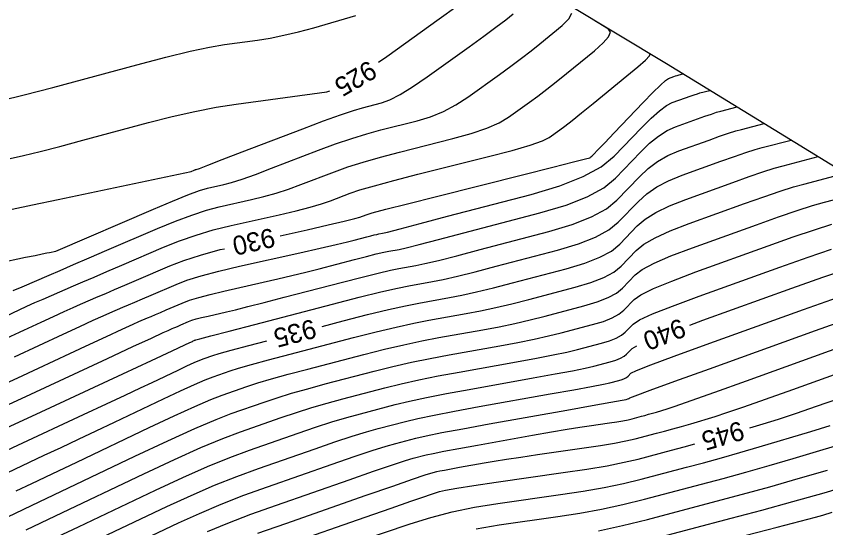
# Model space of a CAD drawing. Extents: x 2175772 to 2185556, y 721391 to 722853.
# Drawn here: x 2178888.4 to 2179007.5, y 722098.3 to 722173.5 of the extents above; entities that cross this region are included whole.
import ezdxf

# ---------------------------------------------------------------- set-up
doc = ezdxf.new("R2010")
doc.units = 0
for name, color, linetype in [('DT_X_Contour_Major', 7, 'Continuous'), ('DT_X_Contour_Minor', 7, 'Continuous'), ('DT_X_TIN_Hull', 7, 'Continuous')]:
    doc.layers.add(name, color=color, linetype=linetype)

msp = doc.modelspace()

# ---------------------------------------------------------------- linework, layer by layer
at = {"layer": 'DT_X_Contour_Major'}
for points in [[(2178941.68, 722166.78), (2178942.86, 722167.62), (2178950.57, 722173.15), (2178953.17, 722175.02), (2178955.21, 722176.5), (2178956.67, 722177.59), (2178957.56, 722178.28), (2178959.18, 722179.6), (2178959.51, 722180.16), (2178959.28, 722180.85), (2178958.49, 722181.66), (2178957.15, 722182.6), (2178949.59, 722187.28)], [(2178927.18, 722141.26), (2178931.14, 722142.15), (2178934.27, 722142.86), (2178936.62, 722143.41), (2178938.16, 722143.79), (2178938.9, 722144), (2178939.82, 722144.36), (2178940.72, 722144.62), (2178942.75, 722145.16), (2178945.9, 722145.97), (2178950.17, 722147.05), (2178963.06, 722150.3), (2178967.29, 722151.36), (2178970.32, 722152.13), (2178972.13, 722152.59), (2178972.75, 722152.75), (2178972.77, 722152.76), (2178972.79, 722152.78), (2178972.82, 722152.8), (2178972.85, 722152.83), (2178972.9, 722152.87), (2178973.05, 722152.98), (2178973.29, 722153.23), (2178973.92, 722153.89), (2178974.94, 722154.95), (2178976.34, 722156.41), (2178980.59, 722160.87), (2178982.02, 722162.34), (2178983.12, 722163.42), (2178983.89, 722164.11), (2178984.34, 722164.41), (2178985.09, 722164.68), (2178985.35, 722164.77), (2178985.57, 722164.84), (2178985.75, 722164.9), (2178985.89, 722164.94), (2178986.45, 722165.09)], [(2178887.49, 722152.64), (2178889.45, 722153.08), (2178891.88, 722153.67), (2178894.78, 722154.41), (2178898.16, 722155.31), (2178907.8, 722157.9), (2178911.32, 722158.8), (2178914.65, 722159.55), (2178917.78, 722160.16), (2178920.73, 722160.61), (2178934.04, 722162.41), (2178934.48, 722162.58)], [(2178933.35, 722127.95), (2178936.45, 722128.75), (2178940.06, 722129.68), (2178943.13, 722130.42), (2178945.64, 722130.99), (2178947.6, 722131.38), (2178952.09, 722132.18), (2178953.93, 722132.54), (2178956.09, 722133.02), (2178958.58, 722133.62), (2178961.38, 722134.34), (2178969.28, 722136.42), (2178971.99, 722137.23), (2178974.2, 722138.1), (2178975.92, 722139.03), (2178977.14, 722140.02), (2178979.72, 722142.72), (2178980.89, 722143.73), (2178982.47, 722144.71), (2178984.46, 722145.68), (2178986.85, 722146.62), (2178993.77, 722149.12), (2178996.17, 722149.97), (2178998.21, 722150.66), (2178999.87, 722151.19), (2179001.17, 722151.56), (2179006.32, 722152.9)], [(2178987.46, 722128.15), (2178989.36, 722128.84), (2179002.44, 722133.56), (2179007, 722135.17), (2179010.85, 722136.48), (2179014, 722137.48), (2179016.44, 722138.18), (2179026.2, 722140.71)], [(2178886.93, 722126.21), (2178892.04, 722128.59), (2178893.84, 722129.42), (2178895.4, 722130.14), (2178896.73, 722130.73), (2178897.83, 722131.21), (2178900.43, 722132.33), (2178901.52, 722132.8), (2178902.82, 722133.36), (2178904.33, 722134.01), (2178906.06, 722134.75), (2178910.95, 722136.85), (2178913, 722137.64), (2178915.47, 722138.43), (2178918.37, 722139.23), (2178919, 722139.37)], [(2178996.28, 722113.03), (2178998.23, 722113.61), (2179000.51, 722114.32), (2179003.13, 722115.18), (2179006.08, 722116.2), (2179009.38, 722117.37), (2179018.63, 722120.7), (2179022.05, 722121.9), (2179025.37, 722122.98), (2179028.59, 722123.94), (2179031.72, 722124.8), (2179046.08, 722128.53)], [(2178885.32, 722108.97), (2178888.62, 722110.49), (2178898.27, 722114.99), (2178901.62, 722116.55), (2178904.41, 722117.86), (2178906.66, 722118.91), (2178908.36, 722119.72), (2178912.17, 722121.53), (2178913.48, 722122.15), (2178914.55, 722122.63), (2178915.39, 722122.99), (2178916, 722123.23), (2178917.3, 722123.68), (2178918.21, 722123.96), (2178919.98, 722124.44), (2178922.6, 722125.14), (2178925.22, 722125.83)], [(2178893.67, 722096.65), (2178897.54, 722098.49), (2178908.83, 722103.86), (2178912.87, 722105.74), (2178916.52, 722107.35), (2178919.79, 722108.69), (2178922.66, 722109.76), (2178929.83, 722112.25), (2178932.41, 722113.13), (2178934.81, 722113.9), (2178937.01, 722114.56), (2178939.01, 722115.11), (2178944.1, 722116.44), (2178946.21, 722116.95), (2178948.73, 722117.5), (2178951.65, 722118.08), (2178954.99, 722118.69), (2178964.42, 722120.37), (2178967.63, 722120.95), (2178970.18, 722121.43), (2178972.08, 722121.82), (2178973.31, 722122.11), (2178975.74, 722122.75), (2178976.57, 722123), (2178977.25, 722123.26), (2178977.78, 722123.55), (2178978.15, 722123.85), (2178978.95, 722124.68), (2178979.64, 722125.07)], [(2178928.19, 722095.9), (2178939.69, 722099.9), (2178943.52, 722101.23), (2178946.4, 722102.23), (2178948.33, 722102.9), (2178949.3, 722103.23), (2178950.61, 722103.67), (2178951.5, 722103.88), (2178953.19, 722104.18), (2178955.68, 722104.57), (2178958.97, 722105.05), (2178968.82, 722106.45), (2178972.28, 722106.97), (2178975.28, 722107.47), (2178977.8, 722107.97), (2178979.87, 722108.45), (2178984.74, 722109.73), (2178986.6, 722110.22), (2178988.21, 722110.67)], [(2178995.76, 722097.23), (2179000.3, 722098.42), (2179003.69, 722099.31), (2179005.93, 722099.91), (2179007.02, 722100.21), (2179008.4, 722100.62)]]:
    msp.add_lwpolyline(points, dxfattribs=at)
at = {"layer": 'DT_X_Contour_Minor'}
for points in [[(2178885.62, 722137.23), (2178889.75, 722138.1), (2178891.13, 722138.39), (2178892.17, 722138.61), (2178892.88, 722138.76), (2178893.25, 722138.83), (2178894.18, 722139.03), (2178908.54, 722145.2), (2178911.35, 722146.38), (2178913.61, 722147.29), (2178915.33, 722147.91), (2178916.51, 722148.25), (2178918.92, 722148.8), (2178920.04, 722149.1), (2178921.58, 722149.6), (2178923.54, 722150.3), (2178925.92, 722151.19), (2178932.84, 722153.84), (2178935.35, 722154.77), (2178937.72, 722155.58), (2178939.94, 722156.27), (2178942.02, 722156.83), (2178947.34, 722158.17), (2178949.3, 722158.77), (2178951.2, 722159.55), (2178953.04, 722160.52), (2178954.81, 722161.67), (2178959.45, 722164.99), (2178961.13, 722166.21), (2178962.68, 722167.37), (2178964.1, 722168.47), (2178965.4, 722169.5), (2178968.69, 722172.19), (2178969.66, 722173.14), (2178970.1, 722173.98)], [(2178886.15, 722161.15), (2178889.54, 722161.98), (2178893.76, 722163.09), (2178906.09, 722166.4), (2178910.36, 722167.52), (2178913.94, 722168.39), (2178916.81, 722169.01), (2178918.99, 722169.38), (2178923.85, 722170.04), (2178925.74, 722170.34), (2178927.75, 722170.74), (2178929.89, 722171.25), (2178932.15, 722171.86), (2178938.34, 722173.64)], [(2178887.77, 722145.19), (2178890.75, 722145.82), (2178894.54, 722146.61), (2178914.11, 722150.72), (2178914.54, 722150.9), (2178914.63, 722150.94), (2178914.69, 722150.97), (2178914.75, 722150.99), (2178914.78, 722151), (2178914.85, 722151.01), (2178915.3, 722151.18), (2178916.57, 722151.66), (2178918.67, 722152.46), (2178921.59, 722153.59), (2178930.51, 722157), (2178933.56, 722158.15), (2178936.05, 722159.05), (2178937.96, 722159.7), (2178939.3, 722160.09), (2178942.1, 722160.8), (2178943.31, 722161.24), (2178944.83, 722162.02), (2178946.68, 722163.16), (2178948.83, 722164.65), (2178955.01, 722169.07), (2178957.15, 722170.62), (2178958.94, 722171.94), (2178960.39, 722173.03), (2178961.48, 722173.89)], [(2178887.9, 722133.2), (2178889.24, 722133.78), (2178893.19, 722135.48), (2178894.83, 722136.18), (2178896.8, 722137.03), (2178899.09, 722138.01), (2178901.71, 722139.13), (2178909.12, 722142.32), (2178911.77, 722143.41), (2178914.18, 722144.31), (2178916.33, 722145.01), (2178918.24, 722145.51), (2178922.99, 722146.58), (2178924.79, 722147.02), (2178926.59, 722147.53), (2178928.41, 722148.13), (2178930.25, 722148.79), (2178935.16, 722150.68), (2178937.14, 722151.39), (2178939.4, 722152.11), (2178941.93, 722152.84), (2178944.73, 722153.57), (2178952.58, 722155.55), (2178955.3, 722156.3), (2178957.58, 722157.08), (2178959.41, 722157.87), (2178960.79, 722158.7), (2178963.89, 722160.92), (2178965.1, 722161.8), (2178966.41, 722162.8), (2178967.81, 722163.9), (2178969.31, 722165.11), (2178973.44, 722168.48), (2178974.73, 722169.63), (2178975.51, 722170.54), (2178975.77, 722171.21), (2178975.51, 722171.65), (2178973.11, 722173.13)], [(2178885.73, 722128.95), (2178888.79, 722130.37), (2178889.94, 722130.91), (2178891.12, 722131.44), (2178892.32, 722131.97), (2178893.54, 722132.5), (2178896.81, 722133.9), (2178898.17, 722134.49), (2178899.81, 722135.19), (2178901.71, 722136.01), (2178903.88, 722136.94), (2178910.03, 722139.58), (2178912.38, 722140.53), (2178914.82, 722141.37), (2178917.35, 722142.12), (2178919.97, 722142.76), (2178927.06, 722144.36), (2178929.53, 722144.94), (2178931.6, 722145.47), (2178933.28, 722145.96), (2178934.57, 722146.4), (2178937.49, 722147.52), (2178938.93, 722148.01), (2178941.08, 722148.63), (2178943.92, 722149.4), (2178947.45, 722150.31), (2178957.82, 722152.92), (2178961.3, 722153.83), (2178963.95, 722154.6), (2178965.77, 722155.23), (2178966.77, 722155.72), (2178968.33, 722156.84), (2178969.08, 722157.4), (2178970.14, 722158.23), (2178971.53, 722159.34), (2178973.23, 722160.72), (2178978.19, 722164.78), (2178979.81, 722166.12), (2178980.92, 722167.11), (2178981.52, 722167.73), (2178981.63, 722168), (2178980.95, 722168.42)], [(2178888.13, 722123.47), (2178895.29, 722126.8), (2178897.73, 722127.94), (2178899.69, 722128.84), (2178901.15, 722129.5), (2178902.12, 722129.93), (2178904.05, 722130.76), (2178904.86, 722131.11), (2178905.82, 722131.52), (2178906.95, 722132), (2178908.23, 722132.56), (2178911.87, 722134.12), (2178913.48, 722134.72), (2178915.57, 722135.37), (2178918.16, 722136.06), (2178921.23, 722136.78), (2178930.09, 722138.78), (2178933.08, 722139.45), (2178935.41, 722139.99), (2178937.08, 722140.38), (2178938.1, 722140.63), (2178939.92, 722141.1), (2178940.54, 722141.26), (2178941.04, 722141.39), (2178941.43, 722141.48), (2178941.69, 722141.53), (2178942.22, 722141.63), (2178942.97, 722141.81), (2178944.82, 722142.29), (2178947.78, 722143.06), (2178951.83, 722144.13), (2178964.11, 722147.36), (2178968.32, 722148.62), (2178971.76, 722149.98), (2178974.43, 722151.42), (2178976.32, 722152.95), (2178980.34, 722157.16), (2178981.75, 722158.57), (2178982.97, 722159.66), (2178984, 722160.42), (2178984.84, 722160.85), (2178986.82, 722161.57), (2178987.51, 722161.81), (2178988.1, 722162.01), (2178988.57, 722162.16), (2178988.94, 722162.27), (2178990.42, 722162.65)], [(2178886.04, 722119.21), (2178889.32, 722120.72), (2178898.55, 722125.02), (2178901.63, 722126.45), (2178903.97, 722127.53), (2178905.56, 722128.27), (2178906.41, 722128.65), (2178907.68, 722129.19), (2178908.2, 722129.42), (2178908.83, 722129.69), (2178909.57, 722130), (2178910.41, 722130.36), (2178912.79, 722131.38), (2178913.84, 722131.78), (2178915.21, 722132.2), (2178916.9, 722132.65), (2178918.91, 722133.13), (2178924.7, 722134.43), (2178926.84, 722134.92), (2178928.93, 722135.42), (2178930.96, 722135.92), (2178932.93, 722136.42), (2178938.13, 722137.78), (2178939.9, 722138.23), (2178941.33, 722138.59), (2178942.42, 722138.84), (2178943.16, 722138.99), (2178944.69, 722139.26), (2178945.71, 722139.49), (2178947.64, 722139.97), (2178950.48, 722140.7), (2178954.22, 722141.68), (2178965.4, 722144.63), (2178969.24, 722145.78), (2178972.37, 722147.01), (2178974.8, 722148.32), (2178976.53, 722149.72), (2178980.19, 722153.55), (2178981.54, 722154.86), (2178982.85, 722155.92), (2178984.12, 722156.73), (2178985.34, 722157.29), (2178988.56, 722158.45), (2178989.68, 722158.85), (2178990.63, 722159.17), (2178991.4, 722159.42), (2178992, 722159.59), (2178994.4, 722160.21)], [(2178886.6, 722116.17), (2178890.52, 722117.98), (2178901.8, 722123.23), (2178905.53, 722124.97), (2178908.25, 722126.23), (2178909.98, 722127.03), (2178910.7, 722127.36), (2178911.3, 722127.62), (2178911.55, 722127.72), (2178911.84, 722127.85), (2178912.19, 722128), (2178912.58, 722128.17), (2178913.7, 722128.65), (2178914.2, 722128.84), (2178914.84, 722129.04), (2178915.64, 722129.25), (2178916.58, 722129.47), (2178919.31, 722130.08), (2178920.6, 722130.39), (2178922.45, 722130.85), (2178924.84, 722131.46), (2178927.77, 722132.22), (2178936.34, 722134.45), (2178939.26, 722135.2), (2178941.62, 722135.79), (2178943.42, 722136.2), (2178944.64, 722136.46), (2178947.15, 722136.9), (2178948.45, 722137.17), (2178950.46, 722137.65), (2178953.18, 722138.34), (2178956.6, 722139.23), (2178966.69, 722141.89), (2178970.16, 722142.93), (2178972.98, 722144.04), (2178975.18, 722145.22), (2178976.73, 722146.48), (2178980.03, 722149.94), (2178981.32, 722151.15), (2178982.72, 722152.19), (2178984.23, 722153.05), (2178985.84, 722153.74), (2178990.29, 722155.34), (2178991.84, 722155.89), (2178993.15, 722156.34), (2178994.22, 722156.68), (2178995.05, 722156.91), (2178998.37, 722157.77)], [(2178886.93, 722113.02), (2178891.29, 722115.04), (2178904.05, 722120.98), (2178908.25, 722122.94), (2178911.3, 722124.35), (2178913.18, 722125.23), (2178913.9, 722125.57), (2178914.28, 722125.75), (2178914.41, 722125.81), (2178914.52, 722125.86), (2178914.61, 722125.9), (2178914.67, 722125.92), (2178914.8, 722125.97), (2178915.38, 722126.12), (2178917.01, 722126.55), (2178919.71, 722127.26), (2178923.47, 722128.24), (2178934.91, 722131.22), (2178938.83, 722132.22), (2178942.01, 722133.01), (2178944.44, 722133.57), (2178946.12, 722133.92), (2178949.62, 722134.54), (2178951.19, 722134.86), (2178953.28, 722135.34), (2178955.88, 722135.98), (2178958.99, 722136.79), (2178967.98, 722139.16), (2178971.07, 722140.08), (2178973.59, 722141.07), (2178975.55, 722142.13), (2178976.93, 722143.25), (2178979.88, 722146.33), (2178981.11, 722147.44), (2178982.6, 722148.45), (2178984.34, 722149.36), (2178986.35, 722150.18), (2178992.03, 722152.23), (2178994.01, 722152.93), (2178995.68, 722153.5), (2178997.05, 722153.93), (2178998.11, 722154.24), (2179002.35, 722155.34)], [(2178885.94, 722105.95), (2178892.49, 722109), (2178894.98, 722110.16), (2178897.53, 722111.36), (2178900.14, 722112.59), (2178902.82, 722113.87), (2178910.05, 722117.31), (2178912.54, 722118.48), (2178914.59, 722119.41), (2178916.18, 722120.09), (2178917.33, 722120.53), (2178919.81, 722121.39), (2178921.05, 722121.79), (2178922.95, 722122.33), (2178925.48, 722123.02), (2178928.65, 722123.86), (2178937.98, 722126.29), (2178941.29, 722127.13), (2178944.25, 722127.84), (2178946.84, 722128.41), (2178949.08, 722128.84), (2178954.55, 722129.82), (2178956.67, 722130.22), (2178958.91, 722130.7), (2178961.28, 722131.26), (2178963.77, 722131.89), (2178970.57, 722133.69), (2178972.91, 722134.39), (2178974.81, 722135.13), (2178976.29, 722135.93), (2178977.34, 722136.78), (2178979.57, 722139.12), (2178980.68, 722140.02), (2178982.35, 722140.98), (2178984.57, 722141.99), (2178987.35, 722143.07), (2178995.5, 722146.01), (2178998.34, 722147.01), (2179000.74, 722147.83), (2179002.7, 722148.45), (2179004.22, 722148.88), (2179010.3, 722150.46)], [(2178888.34, 722103.77), (2178890.64, 722104.86), (2178893.63, 722106.27), (2178897.28, 722108.01), (2178907.94, 722113.09), (2178911.61, 722114.81), (2178914.62, 722116.18), (2178916.97, 722117.19), (2178918.67, 722117.84), (2178922.31, 722119.11), (2178923.89, 722119.63), (2178925.91, 722120.23), (2178928.36, 722120.91), (2178931.24, 722121.67), (2178939.51, 722123.83), (2178942.52, 722124.59), (2178945.37, 722125.25), (2178948.05, 722125.83), (2178950.55, 722126.3), (2178957.02, 722127.45), (2178959.41, 722127.9), (2178961.73, 722128.38), (2178963.98, 722128.9), (2178966.15, 722129.45), (2178971.86, 722130.95), (2178973.82, 722131.54), (2178975.42, 722132.17), (2178976.66, 722132.84), (2178977.54, 722133.55), (2178979.41, 722135.51), (2178980.46, 722136.31), (2178982.22, 722137.24), (2178984.68, 722138.31), (2178987.85, 722139.51), (2178997.24, 722142.89), (2179000.5, 722144.05), (2179003.27, 722144.99), (2179005.52, 722145.71), (2179007.28, 722146.21), (2179014.28, 722148.03)], [(2178887.11, 722099.95), (2178891.74, 722102.16), (2178905.83, 722108.86), (2178910.67, 722111.14), (2178914.65, 722112.95), (2178917.76, 722114.28), (2178920, 722115.15), (2178924.82, 722116.82), (2178926.73, 722117.46), (2178928.88, 722118.12), (2178931.24, 722118.79), (2178933.83, 722119.49), (2178941.04, 722121.36), (2178943.75, 722122.04), (2178946.49, 722122.67), (2178949.25, 722123.24), (2178952.03, 722123.77), (2178959.49, 722125.09), (2178962.15, 722125.58), (2178964.55, 722126.07), (2178966.68, 722126.54), (2178968.54, 722127), (2178973.15, 722128.22), (2178974.74, 722128.69), (2178976.03, 722129.2), (2178977.03, 722129.74), (2178977.75, 722130.32), (2178979.26, 722131.9), (2178980.25, 722132.6), (2178982.1, 722133.51), (2178984.8, 722134.62), (2178988.35, 722135.95), (2178998.97, 722139.78), (2179002.67, 722141.09), (2179005.8, 722142.15), (2179008.35, 722142.97)], [(2178889.83, 722098.04), (2178894.16, 722100.1), (2178907.12, 722106.27), (2178911.65, 722108.39), (2178915.53, 722110.13), (2178918.76, 722111.48), (2178921.33, 722112.46), (2178927.32, 722114.54), (2178929.57, 722115.3), (2178931.84, 722116.01), (2178934.12, 722116.68), (2178936.42, 722117.3), (2178942.57, 722118.9), (2178944.98, 722119.5), (2178947.61, 722120.08), (2178950.45, 722120.66), (2178953.51, 722121.23), (2178961.95, 722122.73), (2178964.89, 722123.27), (2178967.36, 722123.75), (2178969.38, 722124.18), (2178970.93, 722124.55), (2178974.45, 722125.48), (2178975.66, 722125.84), (2178976.64, 722126.23), (2178977.41, 722126.64), (2178977.95, 722127.08), (2178979.1, 722128.29), (2178980.03, 722128.89), (2178981.97, 722129.77), (2178984.91, 722130.94), (2178988.85, 722132.4), (2179000.71, 722136.67), (2179004.84, 722138.13), (2179008.32, 722139.32)], [(2178900.93, 722096.89), (2178910.54, 722101.46), (2178914.08, 722103.1), (2178917.51, 722104.58), (2178920.81, 722105.9), (2178924, 722107.07), (2178932.33, 722109.97), (2178935.25, 722110.97), (2178937.77, 722111.79), (2178939.89, 722112.45), (2178941.6, 722112.93), (2178945.63, 722113.97), (2178947.44, 722114.41), (2178949.85, 722114.91), (2178952.86, 722115.49), (2178956.47, 722116.15), (2178966.89, 722118.01), (2178970.37, 722118.63), (2178973, 722119.12), (2178974.78, 722119.46), (2178975.7, 722119.66), (2178977.03, 722120.01), (2178977.49, 722120.15), (2178977.86, 722120.29), (2178978.15, 722120.45), (2178978.36, 722120.62), (2178978.79, 722121.07), (2178979.6, 722121.46), (2178981.72, 722122.3), (2178985.14, 722123.57), (2178989.86, 722125.28), (2179004.18, 722130.45), (2179009.17, 722132.21)], [(2178904.31, 722095.28), (2178912.25, 722099.06), (2178915.3, 722100.46), (2178918.5, 722101.81), (2178921.84, 722103.11), (2178925.33, 722104.38), (2178934.84, 722107.68), (2178938.09, 722108.8), (2178940.74, 722109.68), (2178942.77, 722110.33), (2178944.19, 722110.74), (2178947.16, 722111.51), (2178948.67, 722111.86), (2178950.97, 722112.33), (2178954.06, 722112.91), (2178957.94, 722113.61), (2178969.35, 722115.64), (2178973.11, 722116.31), (2178975.82, 722116.8), (2178977.48, 722117.1), (2178978.09, 722117.21), (2178978.32, 722117.28), (2178978.4, 722117.3), (2178978.47, 722117.33), (2178978.52, 722117.35), (2178978.56, 722117.38), (2178978.64, 722117.46), (2178979.39, 722117.75), (2178981.6, 722118.56), (2178985.25, 722119.89), (2178990.36, 722121.73), (2179005.92, 722127.33), (2179011.33, 722129.25)], [(2178916.51, 722097.81), (2178919.48, 722099.03), (2178922.87, 722100.32), (2178926.66, 722101.68), (2178937.34, 722105.39), (2178940.93, 722106.64), (2178943.7, 722107.58), (2178945.65, 722108.21), (2178946.78, 722108.55), (2178948.69, 722109.05), (2178949.7, 722109.28), (2178951.28, 722109.6), (2178953.45, 722110.01), (2178956.2, 722110.5), (2178964.3, 722111.94), (2178967.1, 722112.44), (2178969.42, 722112.83), (2178971.27, 722113.14), (2178972.64, 722113.35), (2178975.66, 722113.78), (2178976.72, 722113.93), (2178977.62, 722114.08), (2178978.37, 722114.23), (2178978.96, 722114.37), (2178980.33, 722114.73), (2178980.86, 722114.87), (2178981.4, 722115.02), (2178981.97, 722115.18), (2178982.55, 722115.35), (2178984.14, 722115.82), (2178985.31, 722116.21), (2178987.65, 722117.03), (2178991.14, 722118.28), (2178995.8, 722119.95), (2179009.77, 722124.98)], [(2178923.89, 722097.53), (2178928, 722098.99), (2178939.85, 722103.11), (2178943.77, 722104.47), (2178946.67, 722105.47), (2178948.54, 722106.1), (2178949.37, 722106.36), (2178950.22, 722106.59), (2178950.67, 722106.69), (2178951.38, 722106.83), (2178952.34, 722107.01), (2178953.57, 722107.23), (2178957.18, 722107.88), (2178958.68, 722108.13), (2178960.5, 722108.42), (2178962.61, 722108.74), (2178965.04, 722109.09), (2178971.91, 722110.07), (2178974.31, 722110.42), (2178976.37, 722110.77), (2178978.06, 722111.1), (2178979.41, 722111.41), (2178982.54, 722112.23), (2178983.73, 722112.55), (2178984.97, 722112.89), (2178986.25, 722113.25), (2178987.58, 722113.64), (2178991.18, 722114.72), (2178992.91, 722115.27), (2178995.39, 722116.11), (2178998.61, 722117.24), (2179002.59, 722118.66), (2179014.2, 722122.84)], [(2178938.3, 722096.2), (2178946.29, 722098.9), (2178949.34, 722099.84), (2178952.51, 722100.66), (2178955.8, 722101.35), (2178959.2, 722101.9), (2178968.43, 722103.21), (2178971.77, 722103.72), (2178974.86, 722104.28), (2178977.71, 722104.87), (2178980.32, 722105.5), (2178986.95, 722107.23), (2178989.48, 722107.9), (2178992.11, 722108.63), (2178994.83, 722109.41), (2178997.64, 722110.24), (2179005.28, 722112.51), (2179008.11, 722113.37)], [(2178956.01, 722098.16), (2178959.43, 722098.76), (2178968.03, 722099.98), (2178971.25, 722100.48), (2178974.45, 722101.08), (2178977.62, 722101.76), (2178980.77, 722102.54), (2178989.15, 722104.73), (2178992.35, 722105.58), (2178995.67, 722106.5), (2178999.11, 722107.48), (2179002.67, 722108.53), (2179012.33, 722111.41)], [(2178974.03, 722097.88), (2178977.53, 722098.66), (2178981.23, 722099.58), (2178991.35, 722102.23), (2178995.22, 722103.26), (2178999.24, 722104.37), (2179003.4, 722105.56), (2179007.7, 722106.83)], [(2178981.68, 722096.62), (2178993.56, 722099.73), (2178998.05, 722100.93), (2179002.6, 722102.18), (2179007.23, 722103.5), (2179011.92, 722104.88)]]:
    msp.add_lwpolyline(points, dxfattribs=at)
at = {"layer": 'DT_X_TIN_Hull'}
msp.add_lwpolyline([(2179107.62, 722089.39), (2179075.12, 722109.69), (2179069.22, 722113.13), (2179059.79, 722118.52), (2179054.81, 722121.98), (2179049.44, 722125.39), (2179049.52, 722126.42), (2178984.03, 722166.57), (2178919.21, 722205.54), (2178909.71, 722210.4), (2178906.79, 722212.51), (2178903.07, 722214.83), (2178899.76, 722216.57), (2178897.01, 722218.1), (2178892.62, 722221.15), (2178877.64, 722214.96), (2178841.51, 722186.7), (2178759.74, 722159.66), (2178721.08, 722141.18), (2178706.95, 722109.71), (2178684.5, 722059.42)], dxfattribs=at)

# ---------------------------------------------------------------- texts
at = {"layer": 'DT_X_Contour_Major'}
for s, rotation, p in [('925', 210.2877, (2178940.29, 722167.17)), ('930', 192.9436, (2178926.04, 722142.45)), ('935', 194.6086, (2178932.05, 722129.06)), ('940', 201.4537, (2178986.12, 722129.2)), ('945', 196.3331, (2178994.94, 722114.08))]:
    msp.add_text(s, height=2.8, rotation=rotation, dxfattribs=at).set_placement(p)

doc.saveas('drawing.dxf')
